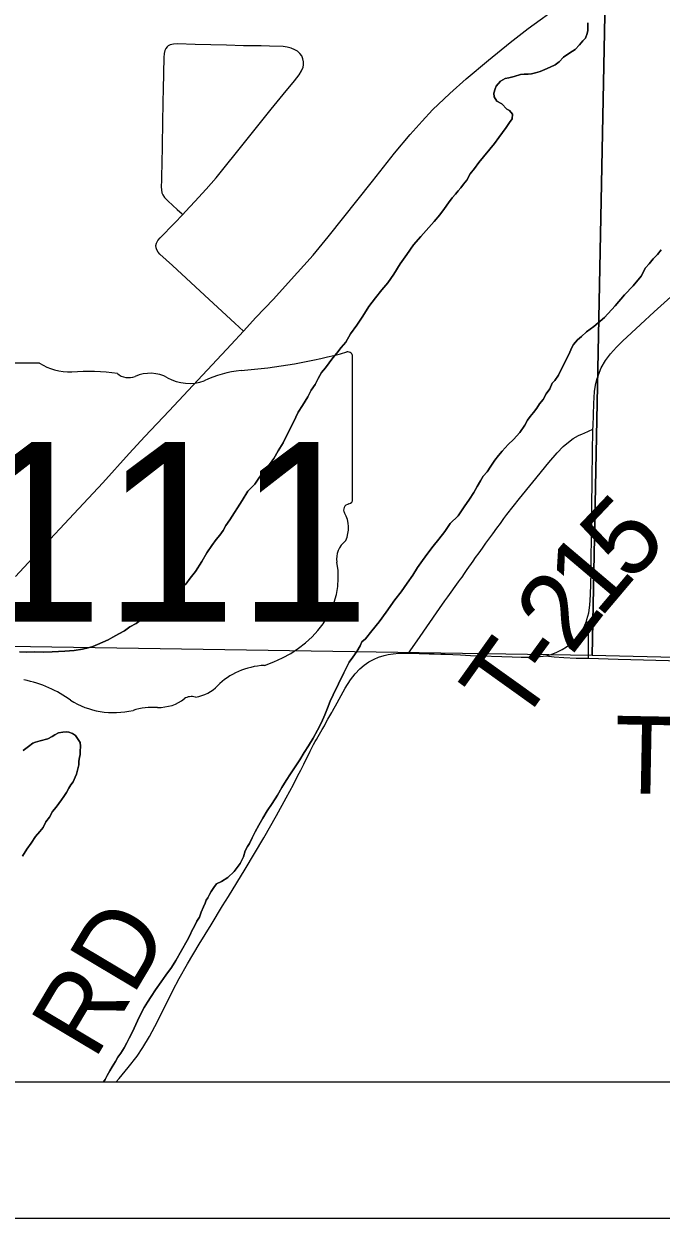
# Model space of a CAD drawing. Extents: x 0 to 34, y 0 to 22.
# Drawn here: x 2.922 to 3.39, y 14 to 14.876 of the extents above; entities that cross this region are included whole.
import ezdxf

# ---------------------------------------------------------------- set-up
doc = ezdxf.new("R2010")
doc.units = 0
for name, color, linetype in [('GM_X_County_Road', 7, 'Continuous'), ('GM_X_County_Road_Text', 7, 'Continuous'), ('GM_X_Major_River', 7, 'Continuous'), ('GM_X_Section', 7, 'Continuous'), ('GM_X_State_Location', 7, 'Continuous'), ('GM_X_State_Route', 7, 'Continuous'), ('GM_X_State_Shield', 7, 'Continuous'), ('GM_X_Township_Road', 7, 'Continuous'), ('GM_X_Township_Road_Text', 7, 'Continuous'), ('SH_Data', 7, 'Continuous')]:
    doc.layers.add(name, color=color, linetype=linetype)

msp = doc.modelspace()

# ---------------------------------------------------------------- linework, layer by layer
at = {"layer": 'GM_X_County_Road'}
for points in [[(3.33957, 14.57872), (3.33961, 14.58079), (3.34011, 14.59754), (3.34066, 14.60616), (3.34136, 14.611), (3.34231, 14.61515), (3.34351, 14.6186), (3.34568, 14.62366), (3.3487, 14.62894), (3.35239, 14.63382), (3.35694, 14.63884), (3.36135, 14.64314), (3.37442, 14.65543), (3.38448, 14.66467), (3.40151, 14.68003)], [(3.33473, 14.43789), (3.33516, 14.43905), (3.33641, 14.44397), (3.33723, 14.44959), (3.33774, 14.45709), (3.33821, 14.47327), (3.33832, 14.48695), (3.33841, 14.49565), (3.33902, 14.5435), (3.33957, 14.57872)], [(3.30487, 14.41245), (3.30881, 14.41349), (3.31299, 14.41502), (3.31699, 14.41698), (3.32024, 14.41899), (3.32377, 14.4217), (3.32697, 14.4248), (3.3298, 14.42825), (3.33186, 14.43147), (3.3336, 14.43488), (3.33473, 14.43789)], [(2.98946, 14.1), (2.99158, 14.10241), (2.99839, 14.11051), (3.00489, 14.11889), (3.00906, 14.12512), (3.01387, 14.13315), (3.01977, 14.14413), (3.03115, 14.16695), (3.03573, 14.17575), (3.0418, 14.18655), (3.05049, 14.20089), (3.05924, 14.21519), (3.06768, 14.22896), (3.0719, 14.23585), (3.08423, 14.256), (3.09788, 14.27898), (3.10713, 14.29517), (3.11433, 14.30824), (3.11957, 14.31814), (3.12217, 14.32309), (3.12397, 14.32635), (3.12504, 14.3286), (3.12717, 14.33305), (3.13181, 14.34245), (3.13442, 14.34735), (3.13563, 14.3495), (3.13654, 14.3511), (3.13777, 14.35324), (3.14084, 14.35848), (3.14242, 14.36104), (3.14351, 14.36326), (3.145, 14.36593), (3.14716, 14.36966), (3.14772, 14.3708), (3.14834, 14.37186), (3.15165, 14.37782), (3.15769, 14.38866), (3.16165, 14.3949), (3.16496, 14.39929), (3.16829, 14.40283), (3.17154, 14.40557), (3.17506, 14.40795), (3.1788, 14.40999), (3.18215, 14.41142), (3.1862, 14.41267), (3.18917, 14.41332), (3.1928, 14.41386), (3.19698, 14.4143), (3.20074, 14.41441), (3.2042, 14.41434)], [(3.2042, 14.41434), (3.21184, 14.41408), (3.21494, 14.41399), (3.21928, 14.41389), (3.22299, 14.41378), (3.22795, 14.41365), (3.23105, 14.41353), (3.24223, 14.41304), (3.24968, 14.41271), (3.28012, 14.41166), (3.28696, 14.41148), (3.29258, 14.41133), (3.29887, 14.41157), (3.30487, 14.41245)]]:
    msp.add_lwpolyline(points, dxfattribs=at)
at = {"layer": 'GM_X_Major_River'}
for points in [[(3.33591, 14.87669), (3.3358, 14.87327), (3.33572, 14.87099), (3.33527, 14.86873), (3.33402, 14.86534), (3.33206, 14.8635), (3.32968, 14.86054), (3.32653, 14.85722), (3.32264, 14.85469), (3.31796, 14.85141), (3.31481, 14.8481), (3.31169, 14.84592), (3.30821, 14.84413), (3.30434, 14.84236), (3.30087, 14.84095), (3.29741, 14.83992), (3.29434, 14.83926), (3.29205, 14.83896), (3.289, 14.83906), (3.28633, 14.83877), (3.28171, 14.8374), (3.27787, 14.83638), (3.27518, 14.83571), (3.2717, 14.83393), (3.26854, 14.83023), (3.26771, 14.82835), (3.26684, 14.82496), (3.26714, 14.82228), (3.26895, 14.81918), (3.27269, 14.81715), (3.27637, 14.81323), (3.27825, 14.8124), (3.28045, 14.80967), (3.28034, 14.80625), (3.27835, 14.80365), (3.27595, 14.79992), (3.27316, 14.79621), (3.27038, 14.7925), (3.26719, 14.78804), (3.25571, 14.77434), (3.25252, 14.76988), (3.24934, 14.7658)], [(3.24934, 14.7658), (3.25252, 14.76988), (3.25571, 14.77434), (3.26719, 14.78804), (3.27038, 14.7925), (3.27316, 14.79621), (3.27595, 14.79992), (3.27835, 14.80365), (3.28034, 14.80625), (3.28045, 14.80967), (3.27825, 14.8124), (3.27637, 14.81323), (3.27269, 14.81715), (3.26895, 14.81918), (3.26714, 14.82228), (3.26684, 14.82496), (3.26771, 14.82835), (3.26854, 14.83023), (3.2717, 14.83393), (3.27518, 14.83571), (3.27787, 14.83638), (3.28171, 14.8374), (3.28633, 14.83877), (3.289, 14.83906), (3.29205, 14.83896), (3.29434, 14.83926), (3.29741, 14.83992), (3.30087, 14.84095), (3.30434, 14.84236), (3.30821, 14.84413), (3.31169, 14.84592), (3.31481, 14.8481), (3.31796, 14.85141), (3.32264, 14.85469), (3.32653, 14.85722), (3.32968, 14.86054), (3.33206, 14.8635), (3.33402, 14.86534), (3.33527, 14.86873), (3.33572, 14.87099), (3.3358, 14.87327), (3.33591, 14.87669)], [(3.24934, 14.7658), (3.24691, 14.76132), (3.24453, 14.75835), (3.24254, 14.75576), (3.24057, 14.75354), (3.23858, 14.75094), (3.23621, 14.74836), (3.23343, 14.74465), (3.23063, 14.74055), (3.22705, 14.73573), (3.22309, 14.73091), (3.21914, 14.72648), (3.21321, 14.71983), (3.20769, 14.71392), (3.2029, 14.70685), (3.1981, 14.69978), (3.19329, 14.69233), (3.1889, 14.68601), (3.18455, 14.68083), (3.17979, 14.6749), (3.17502, 14.66859), (3.1706, 14.66151), (3.1662, 14.65481), (3.16143, 14.6485), (3.15819, 14.64252), (3.15463, 14.63845), (3.15145, 14.63437), (3.14868, 14.63104), (3.1459, 14.62733), (3.14311, 14.62361), (3.14034, 14.62028), (3.13791, 14.6158), (3.13548, 14.61131), (3.13269, 14.60722), (3.13025, 14.60235), (3.12623, 14.59602), (3.12303, 14.59118), (3.11975, 14.58368), (3.1157, 14.5762), (3.11203, 14.56872), (3.10841, 14.56275), (3.10519, 14.55715), (3.102, 14.55269), (3.09843, 14.54824), (3.09485, 14.54342), (3.09125, 14.53821), (3.08614, 14.53306), (3.08211, 14.52634), (3.0729, 14.51219), (3.07011, 14.50809), (3.06808, 14.50436), (3.06569, 14.50101), (3.06292, 14.49768), (3.05973, 14.49322), (3.05614, 14.48802), (3.0525, 14.48167), (3.0477, 14.47422), (3.04374, 14.46941), (3.04055, 14.46495), (3.03699, 14.46088), (3.03344, 14.45719), (3.02877, 14.45392), (3.0237, 14.45029), (3.01862, 14.44627), (3.01316, 14.44227), (3.00811, 14.43901), (3.00421, 14.4361), (2.99955, 14.43359), (2.99565, 14.43067), (2.99139, 14.42853), (2.98713, 14.42601), (2.98364, 14.42423), (2.97978, 14.42245), (2.97591, 14.42068), (2.97244, 14.41927), (2.96898, 14.41824), (2.96476, 14.41724), (2.95863, 14.41631), (2.95176, 14.41577), (2.9426, 14.41531), (2.93612, 14.41515), (2.92928, 14.41538), (2.92356, 14.41519), (2.91861, 14.41535)], [(2.91861, 14.41535), (2.92356, 14.41519), (2.92928, 14.41538), (2.93612, 14.41515), (2.9426, 14.41531), (2.95176, 14.41577), (2.95863, 14.41631), (2.96476, 14.41724), (2.96898, 14.41824), (2.97244, 14.41927), (2.97591, 14.42068), (2.97978, 14.42245), (2.98364, 14.42423), (2.98713, 14.42601), (2.99139, 14.42853), (2.99565, 14.43067), (2.99955, 14.43359), (3.00421, 14.4361), (3.00811, 14.43901), (3.01316, 14.44227), (3.01862, 14.44627), (3.0237, 14.45029), (3.02877, 14.45392), (3.03344, 14.45719), (3.03699, 14.46088), (3.04055, 14.46495), (3.04374, 14.46941), (3.0477, 14.47422), (3.0525, 14.48167), (3.05614, 14.48802), (3.05973, 14.49322), (3.06292, 14.49768), (3.06569, 14.50101), (3.06808, 14.50436), (3.07011, 14.50809), (3.0729, 14.51219), (3.08211, 14.52634), (3.08614, 14.53306), (3.09125, 14.53821), (3.09485, 14.54342), (3.09843, 14.54824), (3.102, 14.55269), (3.10519, 14.55715), (3.10841, 14.56275), (3.11203, 14.56872), (3.1157, 14.5762), (3.11975, 14.58368), (3.12303, 14.59118), (3.12623, 14.59602), (3.13025, 14.60235), (3.13269, 14.60722), (3.13548, 14.61131), (3.13791, 14.6158), (3.14034, 14.62028), (3.14311, 14.62361), (3.1459, 14.62733), (3.14868, 14.63104), (3.15145, 14.63437), (3.15463, 14.63845), (3.15819, 14.64252), (3.16143, 14.6485), (3.1662, 14.65481), (3.1706, 14.66151), (3.17502, 14.66859), (3.17979, 14.6749), (3.18455, 14.68083), (3.1889, 14.68601), (3.19329, 14.69233), (3.1981, 14.69978), (3.2029, 14.70685), (3.20769, 14.71392), (3.21321, 14.71983), (3.21914, 14.72648), (3.22309, 14.73091), (3.22705, 14.73573), (3.23063, 14.74055), (3.23343, 14.74465), (3.23621, 14.74836), (3.23858, 14.75094), (3.24057, 14.75354), (3.24254, 14.75576), (3.24453, 14.75835), (3.24691, 14.76132), (3.24934, 14.7658)], [(3.32248, 14.63517), (3.32411, 14.63854), (3.32532, 14.64078), (3.3281, 14.64411), (3.33123, 14.64667), (3.33476, 14.64998), (3.34022, 14.65398), (3.34805, 14.66057), (3.35593, 14.66906), (3.36267, 14.67721), (3.36897, 14.68385), (3.37491, 14.69088), (3.37815, 14.69686), (3.38091, 14.69981), (3.3837, 14.70352), (3.38685, 14.70684), (3.38962, 14.71018)], [(3.38962, 14.71018), (3.38685, 14.70684), (3.3837, 14.70352), (3.38091, 14.69981), (3.37815, 14.69686), (3.37491, 14.69088), (3.36897, 14.68385), (3.36267, 14.67721), (3.35593, 14.66906), (3.34805, 14.66057), (3.34022, 14.65398), (3.33476, 14.64998), (3.33123, 14.64667), (3.3281, 14.64411), (3.32532, 14.64078), (3.32411, 14.63854), (3.32248, 14.63517)], [(3.01247, 14.15848), (3.01527, 14.16257), (3.01847, 14.16741), (3.02247, 14.17336), (3.02605, 14.17819), (3.03004, 14.18377), (3.03325, 14.18898), (3.04171, 14.20354), (3.04375, 14.20766), (3.04499, 14.21066), (3.047, 14.21402), (3.04864, 14.21777), (3.05064, 14.22074), (3.05191, 14.22451), (3.05355, 14.22826), (3.05478, 14.23088), (3.05561, 14.23313), (3.05681, 14.235), (3.05803, 14.23724), (3.05924, 14.23948), (3.06124, 14.24246), (3.06323, 14.24506), (3.06671, 14.24684), (3.07137, 14.24973), (3.07608, 14.25414), (3.08046, 14.26008), (3.0829, 14.26495), (3.08419, 14.26947), (3.08581, 14.27246), (3.0874, 14.27469), (3.08944, 14.27881), (3.09149, 14.2833), (3.09431, 14.28816), (3.09714, 14.29339), (3.10036, 14.29861), (3.10396, 14.30419), (3.10796, 14.31015), (3.11119, 14.31575), (3.1144, 14.32097), (3.1176, 14.32581), (3.12041, 14.33028), (3.12441, 14.33623), (3.12762, 14.34145), (3.13082, 14.34629), (3.13405, 14.35189), (3.13729, 14.35787), (3.14014, 14.36348), (3.1426, 14.36911), (3.14466, 14.37399), (3.14673, 14.37924), (3.14878, 14.38374), (3.15653, 14.39984), (3.15857, 14.40396), (3.16059, 14.4077), (3.16337, 14.41141), (3.16617, 14.4155), (3.16859, 14.41961), (3.16982, 14.42261), (3.17256, 14.4248), (3.17732, 14.43073), (3.18249, 14.43741), (3.18766, 14.44447), (3.19404, 14.45338), (3.1988, 14.45931), (3.20319, 14.46564), (3.20719, 14.47159), (3.2108, 14.47718), (3.21439, 14.48239), (3.21836, 14.48758), (3.22234, 14.49277), (3.22631, 14.49797), (3.23068, 14.50353), (3.23468, 14.50948), (3.24057, 14.515), (3.24497, 14.5217), (3.24896, 14.52727), (3.25216, 14.53211), (3.25459, 14.5366), (3.257, 14.5407), (3.25901, 14.54406), (3.26179, 14.54739), (3.26458, 14.55148), (3.26739, 14.55596), (3.27016, 14.55929), (3.27294, 14.56262), (3.27728, 14.56742), (3.28121, 14.5711), (3.28594, 14.57627), (3.28953, 14.58147), (3.29156, 14.58521), (3.29355, 14.58781), (3.29593, 14.59077), (3.29832, 14.59412), (3.30032, 14.5971), (3.30309, 14.60043), (3.30513, 14.60455), (3.30791, 14.60826), (3.30957, 14.61239), (3.31153, 14.61423), (3.31432, 14.61832), (3.32248, 14.63517)], [(3.32248, 14.63517), (3.31432, 14.61832), (3.31153, 14.61423), (3.30957, 14.61239), (3.30791, 14.60826), (3.30513, 14.60455), (3.30309, 14.60043), (3.30032, 14.5971), (3.29832, 14.59412), (3.29593, 14.59077), (3.29355, 14.58781), (3.29156, 14.58521), (3.28953, 14.58147), (3.28594, 14.57627), (3.28121, 14.5711), (3.27728, 14.56742), (3.27294, 14.56262), (3.27016, 14.55929), (3.26739, 14.55596), (3.26458, 14.55148), (3.26179, 14.54739), (3.25901, 14.54406), (3.257, 14.5407), (3.25459, 14.5366), (3.25216, 14.53211), (3.24896, 14.52727), (3.24497, 14.5217), (3.24057, 14.515), (3.23468, 14.50948), (3.23068, 14.50353), (3.22631, 14.49797), (3.22234, 14.49277), (3.21836, 14.48758), (3.21439, 14.48239), (3.2108, 14.47718), (3.20719, 14.47159), (3.20319, 14.46564), (3.1988, 14.45931), (3.19404, 14.45338), (3.18766, 14.44447), (3.18249, 14.43741), (3.17732, 14.43073), (3.17256, 14.4248), (3.16982, 14.42261), (3.16859, 14.41961), (3.16617, 14.4155), (3.16337, 14.41141), (3.16059, 14.4077), (3.15857, 14.40396), (3.15653, 14.39984), (3.14878, 14.38374), (3.14673, 14.37924), (3.14466, 14.37399), (3.1426, 14.36911), (3.14014, 14.36348), (3.13729, 14.35787), (3.13405, 14.35189), (3.13082, 14.34629), (3.12762, 14.34145), (3.12441, 14.33623), (3.12041, 14.33028), (3.1176, 14.32581), (3.1144, 14.32097), (3.11119, 14.31575), (3.10796, 14.31015), (3.10396, 14.30419), (3.10036, 14.29861), (3.09714, 14.29339), (3.09431, 14.28816), (3.09149, 14.2833), (3.08944, 14.27881), (3.0874, 14.27469), (3.08581, 14.27246), (3.08419, 14.26947), (3.0829, 14.26495), (3.08046, 14.26008), (3.07608, 14.25414), (3.07137, 14.24973), (3.06671, 14.24684), (3.06323, 14.24506), (3.06124, 14.24246), (3.05924, 14.23948), (3.05803, 14.23724), (3.05681, 14.235), (3.05561, 14.23313), (3.05478, 14.23088), (3.05355, 14.22826), (3.05191, 14.22451), (3.05064, 14.22074), (3.04864, 14.21777), (3.047, 14.21402), (3.04499, 14.21066), (3.04375, 14.20766), (3.04171, 14.20354), (3.03325, 14.18898), (3.03004, 14.18377), (3.02605, 14.17819), (3.02247, 14.17336), (3.01847, 14.16741), (3.01527, 14.16257), (3.01247, 14.15848)], [(2.92125, 14.34298), (2.9232, 14.34444), (2.92515, 14.34589), (2.92828, 14.34845), (2.93021, 14.34915), (2.93367, 14.35017), (2.93942, 14.35151), (2.94253, 14.35331), (2.94447, 14.35438), (2.94718, 14.35581), (2.95025, 14.35647), (2.95292, 14.35677), (2.95481, 14.35632), (2.95745, 14.35547), (2.95968, 14.35388), (2.9615, 14.35115), (2.96295, 14.34882), (2.96325, 14.34615), (2.96312, 14.34235), (2.96305, 14.34007), (2.9626, 14.3378), (2.96213, 14.33515), (2.96205, 14.33249), (2.96161, 14.33061), (2.96075, 14.32759), (2.96031, 14.3257), (2.95947, 14.32345), (2.95784, 14.32008), (2.95625, 14.31785), (2.95464, 14.31524), (2.95302, 14.31225), (2.95102, 14.30927), (2.94942, 14.30666), (2.94743, 14.30406), (2.94544, 14.30147), (2.94267, 14.29813), (2.94063, 14.29402), (2.93786, 14.29069), (2.93582, 14.28657), (2.93345, 14.2836), (2.93028, 14.27991), (2.92708, 14.27507), (2.92389, 14.27061), (2.92068, 14.26539)], [(2.92068, 14.26539), (2.92389, 14.27061), (2.92708, 14.27507), (2.93028, 14.27991), (2.93345, 14.2836), (2.93582, 14.28657), (2.93786, 14.29069), (2.94063, 14.29402), (2.94267, 14.29813), (2.94544, 14.30147), (2.94743, 14.30406), (2.94942, 14.30666), (2.95102, 14.30927), (2.95302, 14.31225), (2.95464, 14.31524), (2.95625, 14.31785), (2.95784, 14.32008), (2.95947, 14.32345), (2.96031, 14.3257), (2.96075, 14.32759), (2.96161, 14.33061), (2.96205, 14.33249), (2.96213, 14.33515), (2.9626, 14.3378), (2.96305, 14.34007), (2.96312, 14.34235), (2.96325, 14.34615), (2.96295, 14.34882), (2.9615, 14.35115), (2.95968, 14.35388), (2.95745, 14.35547), (2.95481, 14.35632), (2.95292, 14.35677), (2.95025, 14.35647), (2.94718, 14.35581), (2.94447, 14.35438), (2.94253, 14.35331), (2.93942, 14.35151), (2.93367, 14.35017), (2.93021, 14.34915), (2.92828, 14.34845), (2.92515, 14.34589), (2.9232, 14.34444), (2.92125, 14.34298)], [(2.98029, 14.1), (2.98133, 14.10168), (2.98295, 14.10467), (2.98496, 14.10803), (2.98658, 14.11102), (2.98899, 14.11475), (2.99062, 14.11812), (2.993, 14.12108), (2.9954, 14.12481), (2.99742, 14.12854), (2.99905, 14.13191), (3.00068, 14.13528), (3.00272, 14.1394), (3.00518, 14.14464), (3.00763, 14.14989), (3.01006, 14.15437), (3.01247, 14.15848)], [(3.01247, 14.15848), (3.01006, 14.15437), (3.00763, 14.14989), (3.00518, 14.14464), (3.00272, 14.1394), (3.00068, 14.13528), (2.99905, 14.13191), (2.99742, 14.12854), (2.9954, 14.12481), (2.993, 14.12108), (2.99062, 14.11812), (2.98899, 14.11475), (2.98658, 14.11102), (2.98496, 14.10803), (2.98295, 14.10467), (2.98133, 14.10168), (2.98029, 14.1)]]:
    msp.add_lwpolyline(points, dxfattribs=at)
at = {"layer": 'GM_X_Section'}
for points in [[(2.36882, 15.43324), (3.35868, 15.41381), (3.33901, 14.41257), (2.35513, 14.42769)], [(4.35758, 15.39266), (4.33594, 14.38845), (3.33901, 14.41257), (3.35868, 15.41381)]]:
    msp.add_lwpolyline(points, close=True, dxfattribs=at)
at = {"layer": 'GM_X_State_Route'}
msp.add_lwpolyline([(2.91551, 14.47067), (2.93416, 14.49068), (2.95844, 14.51649), (2.97961, 14.53924), (2.99897, 14.56078), (3.01063, 14.57329), (3.02838, 14.59205), (3.07399, 14.64079), (3.08297, 14.65051), (3.09213, 14.66043), (3.10501, 14.67391), (3.11588, 14.68585), (3.13401, 14.7063), (3.14506, 14.71971), (3.17761, 14.7606), (3.19383, 14.78101), (3.20541, 14.79487), (3.21411, 14.80464), (3.22184, 14.81278), (3.23448, 14.82481), (3.24658, 14.83556), (3.26277, 14.84918), (3.27871, 14.86214), (3.292, 14.87243), (3.31562, 14.88966)], dxfattribs=at)
at = {"layer": 'GM_X_State_Shield'}
for p, q in [((3.163, 14.52724), (3.163, 14.63192)), ((2.93318, 14.62696), (2.83666, 14.62696)), ((3.16297, 14.52726), (3.163, 14.52724))]:
    msp.add_line(p, q, dxfattribs=at)
for centre, major_axis, start_param, end_param in [((3.0456, 14.89979), (0.34952, 0), 4.814394, 5.042369), ((3.15934, 14.63236), (0.00367, 0), 6.141152, 7.989035), ((2.95617, 14.65019), (0.03703, 0), 4.042523, 4.731795), ((2.96845, 14.51461), (0.13295, 0), 1.404758, 1.657858), ((2.99863, 14.62498), (0.01068, 0), 3.836095, 5.185415), ((3.01431, 14.60185), (0.02221, 0), 0.950623, 2.079405), ((3.09018, 14.56584), (0.07032, 0), 1.699011, 2.107814), ((3.04298, 14.63358), (0.02672, 0), 4.081561, 5.145723), ((3.16215, 14.51955), (0.00568, 0), 1.883978, 3.671073), ((3.15908, 14.52683), (0.00393, 0), 5.05454, 6.418171), ((3.12603, 14.50632), (0.03409, 0), 5.934695, 6.695948), ((3.17614, 14.48343), (0.0248, 0), 2.387724, 3.262537), ((3.06518, 14.47011), (0.08742, 0), 5.101752, 6.440018), ((3.10204, 14.36722), (0.04788, 0), 1.647645, 2.488434), ((2.9024, 14.33349), (0.07897, 0), 0.823519, 1.323587), ((3.04458, 14.37649), (0.00752, 0), 1.147584, 2.315152), ((3.04137, 14.404), (0.02824, 0), 4.937069, 5.64225), ((2.98781, 14.41086), (0.05011, 0), 4.026481, 4.996735), ((3.01677, 14.34167), (0.04118, 0), 1.495662, 1.94098), ((3.02043, 14.39587), (0.0267, 0), 4.691044, 5.507374)]:
    msp.add_ellipse(centre, major_axis=major_axis, ratio=0.8, start_param=start_param, end_param=end_param, dxfattribs=at)
at = {"layer": 'GM_X_Township_Road'}
for points in [[(2.1, 18.40743), (2.1, 14.1), (7.35068, 14.1), (7.35419, 14.31073), (7.37669, 15.31551), (7.38543, 16.36959)], [(3.08297, 14.65051), (3.07658, 14.65639), (3.05784, 14.67367), (3.03092, 14.69857), (3.02163, 14.70692), (3.02031, 14.70841), (3.0193, 14.71023), (3.01885, 14.71157), (3.01869, 14.71339), (3.01921, 14.71513), (3.02016, 14.71701), (3.02189, 14.71901), (3.03233, 14.72966), (3.03844, 14.73617), (3.0404, 14.73825), (3.04713, 14.74558), (3.05563, 14.75462), (3.06296, 14.76304), (3.08474, 14.79016), (3.1034, 14.81345), (3.11199, 14.8241), (3.12032, 14.83411), (3.12373, 14.83848), (3.12564, 14.84149), (3.12671, 14.84418), (3.12707, 14.84585), (3.12713, 14.84812), (3.12664, 14.85031), (3.12569, 14.85239), (3.12435, 14.85425), (3.12263, 14.85578), (3.12065, 14.85697), (3.11788, 14.85806), (3.115, 14.85879), (3.11205, 14.8592), (3.10213, 14.8595), (3.09594, 14.85968), (3.08289, 14.85987), (3.07043, 14.86029), (3.04746, 14.86074), (3.03446, 14.86122), (3.03149, 14.86103), (3.02926, 14.86049), (3.02776, 14.85978), (3.02693, 14.85913), (3.02594, 14.85788), (3.02523, 14.85638), (3.02463, 14.85415), (3.02439, 14.8512), (3.02395, 14.82791), (3.02378, 14.81877), (3.02319, 14.78747), (3.02291, 14.77231), (3.02278, 14.76542), (3.02275, 14.7636), (3.02268, 14.76122), (3.02261, 14.75646), (3.02269, 14.75416), (3.02312, 14.75197), (3.02365, 14.75046), (3.0249, 14.74853), (3.02739, 14.74603), (3.03115, 14.74279), (3.03437, 14.73986), (3.03799, 14.73667)], [(3.2042, 14.41434), (3.21042, 14.42331), (3.22698, 14.44721), (3.23084, 14.45262), (3.23298, 14.45564), (3.24084, 14.46673), (3.24231, 14.46872), (3.24341, 14.47021), (3.24513, 14.47277), (3.24731, 14.47578), (3.25158, 14.48187), (3.25334, 14.48443), (3.25593, 14.4879), (3.25842, 14.49145), (3.26101, 14.49493), (3.26386, 14.49901), (3.26609, 14.50199), (3.26893, 14.50606), (3.27156, 14.50951), (3.27415, 14.51301), (3.27643, 14.51595), (3.28557, 14.52773), (3.29535, 14.53985), (3.3072, 14.55427), (3.31332, 14.56137), (3.31771, 14.56585), (3.32154, 14.56914), (3.32513, 14.57173), (3.32897, 14.57398), (3.33185, 14.57524), (3.33298, 14.57575), (3.33957, 14.57872)], [(3.33623, 14.41064), (3.33634, 14.41631), (3.33629, 14.43003), (3.33629, 14.4325), (3.33596, 14.43464), (3.33473, 14.43789)], [(3.30487, 14.41245), (3.31114, 14.41159), (3.31821, 14.4111), (3.32724, 14.41079), (3.33623, 14.41064)], [(3.33623, 14.41064), (3.35799, 14.41004), (3.40424, 14.40877), (3.43284, 14.40808), (3.44484, 14.40782), (3.47446, 14.40717), (3.50976, 14.40641), (3.55358, 14.40562), (3.58663, 14.40493), (3.62655, 14.40409), (3.65456, 14.40329), (3.69464, 14.40214), (3.71444, 14.40169), (3.72127, 14.40146), (3.73494, 14.40103), (3.76104, 14.40038), (3.78592, 14.40011), (3.79896, 14.39987), (3.81138, 14.39958), (3.81512, 14.3995), (3.83, 14.39932), (3.83681, 14.39924), (3.84119, 14.39915)]]:
    msp.add_lwpolyline(points, dxfattribs=at)
at = {"layer": 'SH_Data'}
for p, q in [((2.1, 14.1), (8.9, 14.1)), ((2, 14), (9, 14))]:
    msp.add_line(p, q, dxfattribs=at)

# ---------------------------------------------------------------- texts
at = {"layer": 'GM_X_County_Road_Text'}
msp.add_text('RD', height=0.056818, rotation=59.23014, dxfattribs=at).set_placement((2.97348, 14.11508))
at = {"layer": 'GM_X_State_Location'}
for s, p in [('s', (2.99451, 14.51015)), ('r', (2.9945, 14.51015))]:
    msp.add_text(s, height=0.000189, dxfattribs=at).set_placement(p)
msp.add_text('111', height=0.000189, rotation=0.00001, dxfattribs=at).set_placement((2.92764, 14.49637))
at = {"layer": 'GM_X_State_Shield'}
msp.add_text('111', height=0.131836, dxfattribs=at).set_placement((2.88198, 14.43751))
at = {"layer": 'GM_X_Township_Road_Text'}
for s, height, rotation, p in [('5', 0.05682, 46.49228, (3.36666, 14.46512)), ('1', 0.05682, 49.77632, (3.34464, 14.43904)), ('2', 0.05682, 52.26308, (3.32363, 14.41187)), ('T', 0.05682, 54.42919, (3.28549, 14.35891)), ('-', 0.05682, 53.87793, (3.31012, 14.39336)), ('T-12', 0.056818, 358.94286, (3.35498, 14.31168))]:
    msp.add_text(s, height=height, rotation=rotation, dxfattribs=at).set_placement(p)

doc.saveas('drawing.dxf')
